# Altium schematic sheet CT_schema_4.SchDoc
size 368 x 309 mm
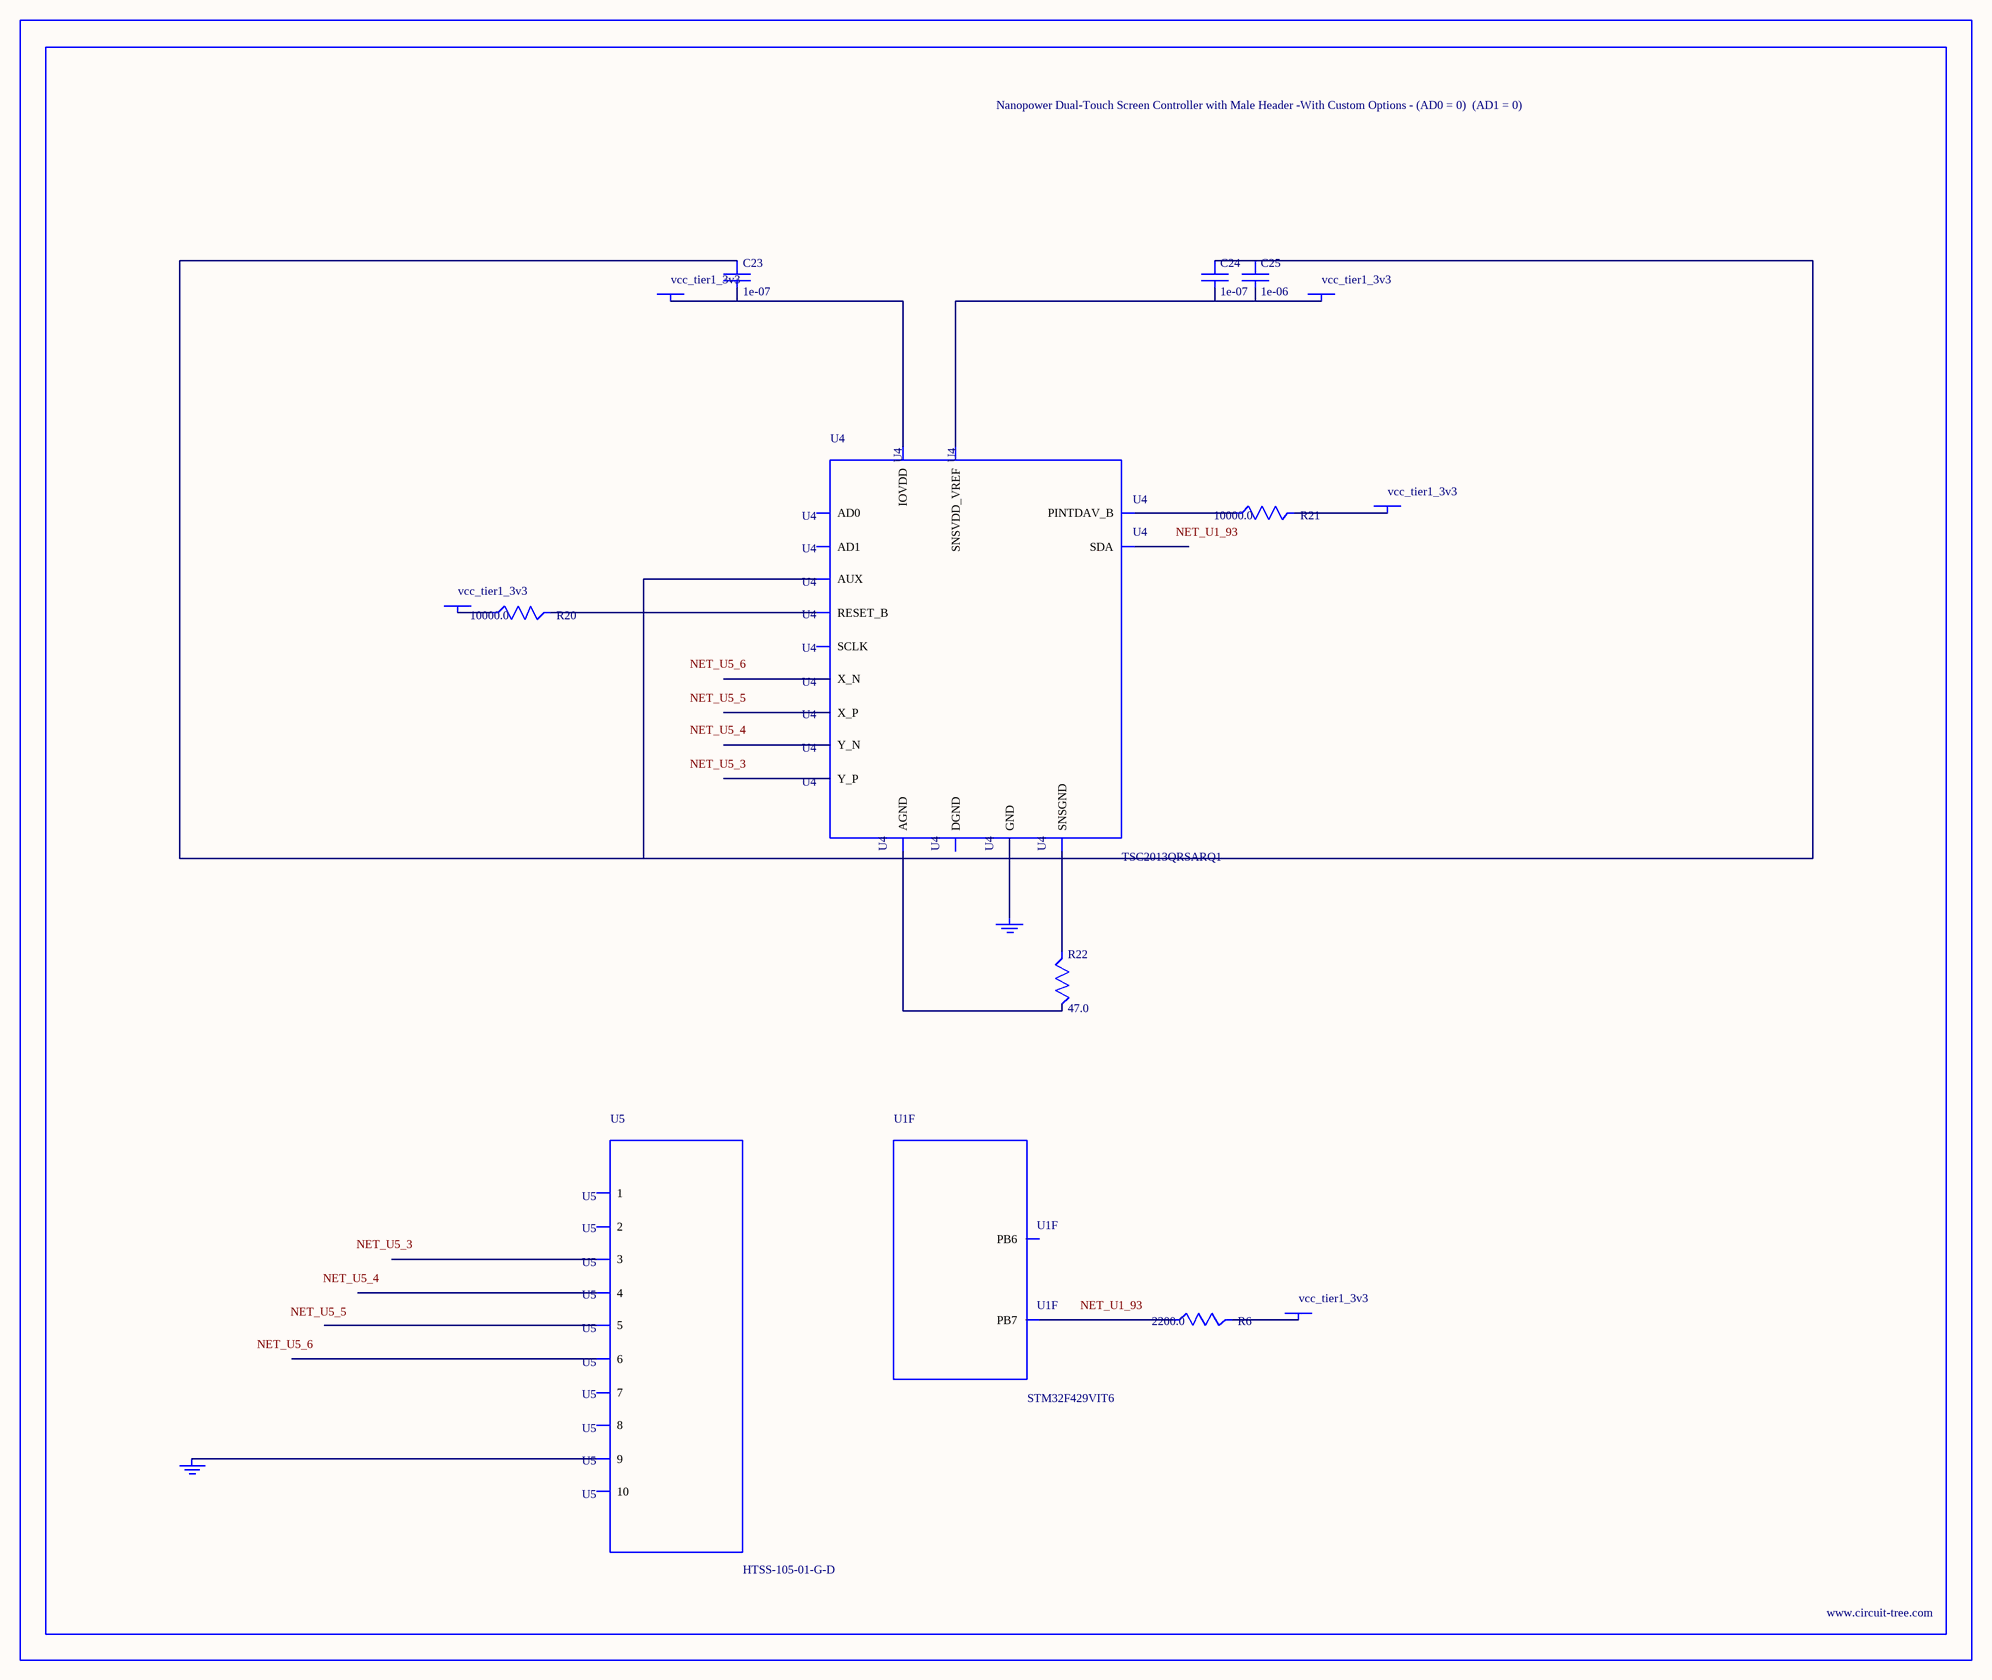
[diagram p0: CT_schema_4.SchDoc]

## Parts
BORDER3  (no value)
C23  1e-07  [C0402]
C24  1e-07  [C0402]
C25  1e-06  [C0603]
GND_INSTANCE_3_0  (no value)
GND_INSTANCE_3_1  (no value)
POWER_INSTANCE_3_0  vcc_tier1_3v3
POWER_INSTANCE_3_1  vcc_tier1_3v3
POWER_INSTANCE_3_2  vcc_tier1_3v3
POWER_INSTANCE_3_3  vcc_tier1_3v3
POWER_INSTANCE_3_4  vcc_tier1_3v3
R6  2200.0  [R0603]
R20  10000.0  [R0603]
R21  10000.0  [R0603]
R22  47.0  [R0603]
U1  STM32F429VIT6  [LQFP100]  (part F of 9)
U4  TSC2013QRSARQ1  [QFN65P400X400X100-17N]
U5  HTSS-105-01-G-D  [HTSS-105-01-G-D]

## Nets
NetC23_1: C23.1 C24.1 C25.1 R22.1 R22.2 U4.8(AUX) U4.9(AGND) U4.15(SNSGND)
NetC23_2: C23.2 POWER_INSTANCE_3_2.0(PWR) U4.7(IOVDD)
NetC24_2: C24.2 C25.2 POWER_INSTANCE_3_3.0(PWR) U4.10(SNSVDD_VREF)
NetGND_INSTANCE_3_0_0: GND_INSTANCE_3_0.0(GND) U4.17(GND)
NetGND_INSTANCE_3_1_0: GND_INSTANCE_3_1.0(GND) U5.9
NetPOWER_INSTANCE_3_0_0: POWER_INSTANCE_3_0.0(PWR) R21.2
NetPOWER_INSTANCE_3_1_0: POWER_INSTANCE_3_1.0(PWR) R20.1
NetPOWER_INSTANCE_3_4_0: POWER_INSTANCE_3_4.0(PWR) R6.2
NetR6_1: R6.1 U1.93(PB7)
NetR20_2: R20.2 U4.5(RESET_B)
NetR21_1: R21.1 U4.4(PINTDAV_B)

Not connected (* = marked no-connect by the designer): U1 92(PB6); U4 1(SDA) 2(SCLK) 3(AD1) 6(DGND) 11(X_P) 12(Y_P) 13(X_N) 14(Y_N) 16(AD0); U5 1 2 3 4 5 6 7 8 10

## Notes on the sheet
- Labels drawn without touching a wire or pin: NET_U1_93, NET_U5_3, NET_U5_4, NET_U5_5, NET_U5_6

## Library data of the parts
BORDER3 = BORDER_PAGE3
C23 C24 = C0402C104K3RACTU
C25 = C0603C105K3RACTU
GND_INSTANCE_3_0 GND_INSTANCE_3_1 = GND
POWER_INSTANCE_3_0-POWER_INSTANCE_3_4 = PWR
R6 = RC0603JR-072K2L
R20 R21 = RC0603JR-0710KL
R22 = RC0603JR-0747RL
